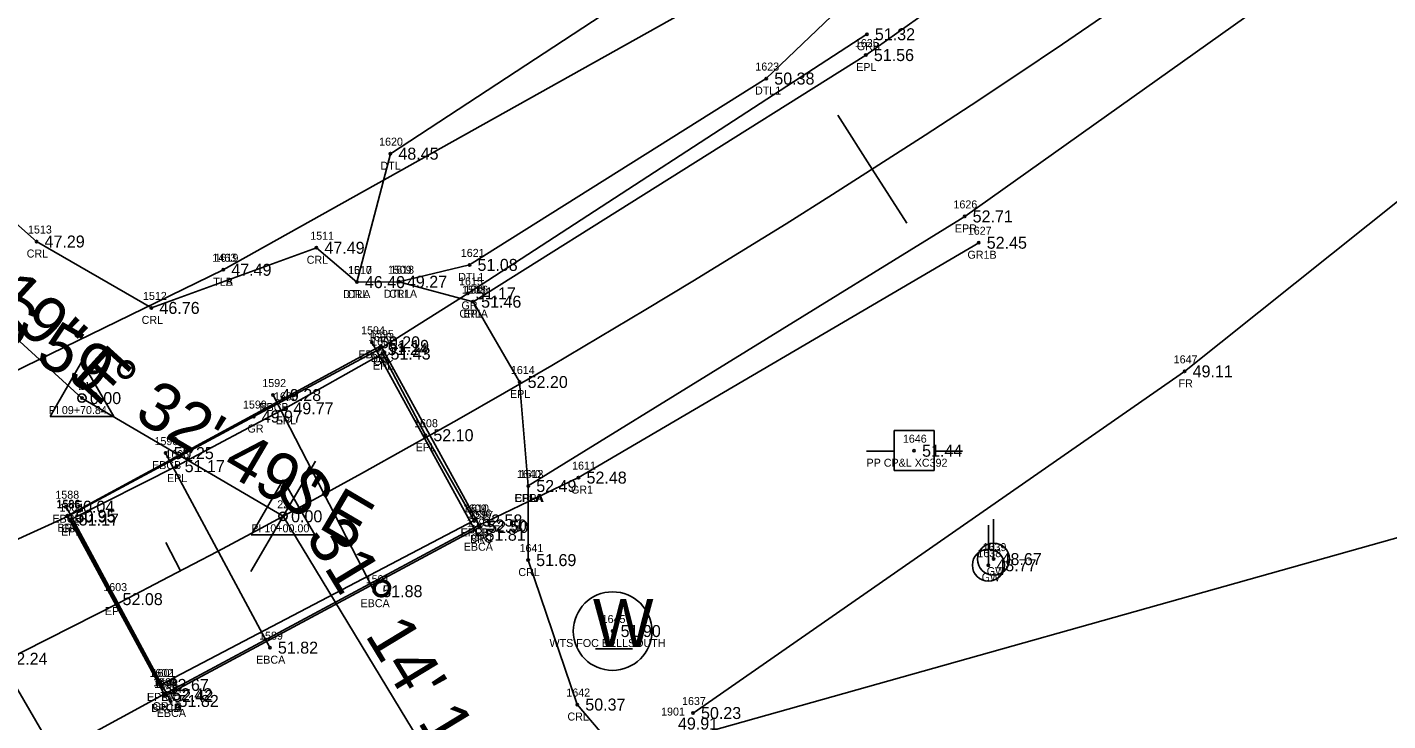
# Model space of a CAD drawing. Extents: x 2420113 to 2422887, y 845323 to 846653.
# Drawn here: x 2421748.2 to 2421918.2, y 845790.5 to 845877.2 of the extents above; entities that cross this region are included whole.
import ezdxf

# ---------------------------------------------------------------- set-up
doc = ezdxf.new("R2010")
doc.units = 0
for name, color, linetype in [('RD_EX_Bridge', 7, 'Continuous'), ('RD_EX_Bridge_txCode', 7, 'Continuous'), ('RD_EX_Fence_Other', 7, 'Continuous'), ('RD_EX_Fence_Other_txCode', 7, 'Continuous'), ('RD_EX_GuardRail', 7, 'Continuous'), ('RD_EX_GuardRail_txCode', 7, 'Continuous'), ('RD_EX_H2O', 7, 'Continuous'), ('RD_EX_H2O_txCode', 7, 'Continuous'), ('RD_EX_Road', 7, 'Continuous'), ('RD_EX_Road_txCode', 7, 'Continuous'), ('RD_EX_TX_Bridge_ELEV', 7, 'Continuous'), ('RD_EX_TX_Fence_Other_ELEV', 7, 'Continuous'), ('RD_EX_TX_GuardRail_ELEV', 7, 'Continuous'), ('RD_EX_TX_H2O_ELEV', 7, 'Continuous'), ('RD_EX_TX_Road_ELEV', 7, 'Continuous'), ('RD_EX_TX_UT_ELEV', 7, 'Continuous'), ('RD_EX_TX_VEG_ELEV', 7, 'Continuous'), ('RD_EX_UT', 7, 'Continuous'), ('RD_EX_UT_txCode', 7, 'Continuous'), ('RD_EX_VEG', 7, 'Continuous'), ('RD_EX_VEG_txCode', 7, 'Continuous'), ('RD_HC_Cl', 7, 'Continuous'), ('RD_HC_Data', 7, 'Continuous'), ('RD_HC_Data_Tic', 7, 'Continuous'), ('RD_HC_Survey_ELEV', 7, 'Continuous'), ('RD_HC_txCode', 7, 'Continuous'), ('RD_SMD_Locator', 7, 'Continuous')]:
    doc.layers.add(name, color=color, linetype=linetype)

msp = doc.modelspace()

# ---------------------------------------------------------------- linework, layer by layer
at = {"layer": 'RD_EX_Bridge'}
for p, q in [((2421804.43, 845813.73), (2421791.23, 845837.78)), ((2421791.53, 845806.67), (2421778.87, 845831.19)), ((2421778.48, 845799.61), (2421765.45, 845823.93)), ((2421766.07, 845792.95), (2421753.01, 845817.23))]:
    msp.add_line(p, q, dxfattribs=at)
msp.add_lwpolyline([(2421765.39, 845793.58), (2421753.17, 845816.1), (2421792.35, 845837.33), (2421804.76, 845814.71), (2421765.39, 845793.58)], dxfattribs=at)
at = {"layer": 'RD_EX_Fence_Other'}
msp.add_lwpolyline([(2421831.36, 845791.44), (2421892.8, 845834.15), (2422007.74, 845925.97), (2422081.95, 845988.07), (2422163.86, 846055.55), (2422242.21, 846120.9), (2422258.64, 846091.49), (2422278.16, 846056.57)], dxfattribs=at)
at = {"layer": 'RD_EX_GuardRail'}
for points in [[(2421687.56, 845786.15), (2421753.19, 845816.01), (2421776.46, 845828.5), (2421792.19, 845836.93), (2421803.2, 845843.9), (2421853.09, 845876.29)], [(2421700.48, 845761.64), (2421736.86, 845778.33), (2421765.25, 845793.79), (2421765.25, 845793.79), (2421804.57, 845814.88), (2421817.05, 845820.87), (2421867.07, 845850.23)]]:
    msp.add_lwpolyline(points, dxfattribs=at)
at = {"layer": 'RD_EX_H2O'}
for points in [[(2421803.88, 845842.86), (2421794.61, 845845.35), (2421789.35, 845845.31), (2421784.3, 845849.6), (2421763.68, 845842.08), (2421749.32, 845850.38), (2421719.73, 845876.64), (2421694.91, 845901.66), (2421677.7, 845939.02), (2421693.6, 845947.01), (2421705.85, 845990.03), (2421703.45, 845999.67)], [(2421789.35, 845845.31), (2421793.54, 845861.36), (2421830.86, 845885.86), (2421856.64, 845909.86), (2421885.29, 845955.58), (2421912.03, 845969.16), (2421958.61, 845996.32), (2421973.32, 845987.17)], [(2421794.61, 845845.35), (2421803.43, 845847.46), (2421840.52, 845870.75), (2421867.66, 845896.73), (2421896.88, 845943.67), (2421923.99, 845959.47), (2421960.72, 845976.98), (2421973.32, 845987.17)], [(2421810.77, 845819.82), (2421810.76, 845810.56), (2421816.9, 845792.5), (2421822.4, 845786.03), (2421848.72, 845738.63), (2421858.75, 845685.13), (2421860.35, 845662.88), (2421845.9, 845650.47), (2421833.11, 845629.75), (2421840.79, 845614.06), (2421848.44, 845579.41), (2421832.04, 845554.52), (2421837.19, 845498.45), (2421811.62, 845484.13), (2421811.72, 845469.11), (2421841.99, 845438.03), (2421875.97, 845424.56), (2421900.41, 845383.13), (2421915.29, 845367.51)]]:
    msp.add_lwpolyline(points, dxfattribs=at)
at = {"layer": 'RD_EX_Road'}
msp.add_line((2421764.83, 845794.95), (2421804.01, 845815.51), dxfattribs=at)
for points in [[(2421810.77, 845819.82), (2421809.69, 845832.82), (2421803.88, 845842.86), (2421852.96, 845873.69), (2421939.48, 845935.12), (2421980.78, 845967.01), (2422140.12, 846092.81), (2422210.03, 846148.43), (2422282.88, 846205.21), (2422291.79, 846212.09), (2422354.49, 846261.98), (2422400.82, 846297.88), (2422417.34, 846311.65), (2422435.4, 846324.77), (2422462.49, 846346.77), (2422472.85, 846354.85), (2422502.3, 846378.16), (2422578.05, 846437.54), (2422605.64, 846459.09), (2422626.64, 846476.17), (2422642.61, 846488.86)], [(2421810.77, 845819.82), (2421865.31, 845853.52), (2421953.26, 845916.07), (2421995.06, 845948.03), (2422068.36, 846005.98), (2422153.46, 846073.36), (2422229.55, 846134.03), (2422245.4, 846145.63), (2422297.08, 846186.88), (2422369.77, 846243.69), (2422382.04, 846253.08), (2422449.02, 846305.97), (2422517.14, 846360.1), (2422592.58, 846419.1), (2422657.51, 846470.1)], [(2421764.83, 845794.95), (2421759.07, 845805.68), (2421753.59, 845815.63), (2421766.83, 845822.3), (2421780.42, 845829.53), (2421792.55, 845836.37), (2421797.91, 845826.17), (2421804.01, 845815.51)], [(2420388.28, 845680.39), (2420441.29, 845692.04), (2420492.62, 845700.7), (2420553.92, 845707.41), (2420607.69, 845710.85), (2420682.38, 845711.26), (2420749.44, 845707.27), (2420795.12, 845703.44), (2420900.28, 845693.42), (2421017.17, 845682.19), (2421113.9, 845672.97), (2421174.87, 845668.16), (2421234.59, 845666.13), (2421293, 845667.25), (2421351.24, 845671.5), (2421419.82, 845681.17), (2421463.19, 845688.63), (2421558.82, 845713.18), (2421614.57, 845730.45), (2421670.73, 845751.42), (2421735.61, 845780.5), (2421750.75, 845787.87), (2421744.67, 845798.22), (2421739.21, 845808.11)]]:
    msp.add_lwpolyline(points, dxfattribs=at)
at = {"layer": 'RD_EX_UT'}
for p, q in [((2421861.48, 845826.74), (2421856.48, 845826.74)), ((2421856.48, 845826.74), (2421856.48, 845821.74)), ((2421861.48, 845821.74), (2421861.48, 845826.74)), ((2421853.04, 845824.18), (2421856.51, 845824.18)), ((2421861.4, 845824.18), (2421865.04, 845824.18)), ((2421856.48, 845821.74), (2421861.48, 845821.74)), ((2421868.92, 845810.68), (2421868.92, 845815.68)), ((2421868.27, 845809.92), (2421868.27, 845814.92)), ((2421819.18, 845799.48), (2421823.81, 845799.48))]:
    msp.add_line(p, q, dxfattribs=at)
for centre, radius in [((2421868.27, 845809.92), 2), ((2421868.92, 845810.68), 2), ((2421821.31, 845801.68), 4.91)]:
    msp.add_circle(centre, radius, dxfattribs=at)
at = {"layer": 'RD_EX_VEG'}
for points in [[(2420990.17, 846190.24), (2420988, 845998.32), (2421000.67, 845894.83), (2421039.72, 845794.91), (2421064.26, 845723.75), (2421180.05, 845716.6), (2421345.47, 845727.16), (2421407.77, 845719.99), (2421650.04, 845787.07), (2421772.66, 845846.85), (2421772.66, 845846.85), (2421889.56, 845912.24), (2422060.37, 846045.26), (2422197.94, 846165.23), (2422281.92, 846227.58), (2422364.58, 846286.67), (2422339.46, 846334.5)], [(2421514.28, 845601.29), (2421515.71, 845632.65), (2421540.03, 845670.81), (2421822.4, 845786.03), (2421822.4, 845786.03), (2421928.63, 845815.98), (2422026.48, 845905.33), (2422114.13, 845963.57), (2422135.16, 845938.99)]]:
    msp.add_lwpolyline(points, dxfattribs=at)
at = {"layer": 'RD_HC_Cl'}
for p, q in [((2421717.97, 845864.51), (2421754.99, 845830.81)), ((2421754.99, 845830.81), (2421780.13, 845816.03)), ((2421780.13, 845816.03), (2421802.52, 845779.12))]:
    msp.add_line(p, q, dxfattribs=at)
msp.add_arc((2421235.71, 846823.95), 1145.56, 264.46476, 308.21213, dxfattribs=at)
at = {"layer": 'RD_HC_Data'}
for p, q in [((2421751.02, 845828.52), (2421754.99, 845835.4)), ((2421754.99, 845835.4), (2421758.96, 845828.52)), ((2421751.02, 845828.52), (2421758.96, 845828.52)), ((2421776.16, 845813.73), (2421780.14, 845820.61)), ((2421780.14, 845820.61), (2421784.1, 845813.73)), ((2421776.16, 845813.73), (2421784.1, 845813.73))]:
    msp.add_line(p, q, dxfattribs=at)
for centre in [(2421754.99, 845830.81), (2421780.13, 845816.03)]:
    msp.add_circle(centre, 0.529, dxfattribs=at)
at = {"layer": 'RD_HC_Data_Tic'}
for p, q in [((2421853.77, 845859.42), (2421849.46, 845866.16)), ((2421853.77, 845859.42), (2421858.09, 845852.69)), ((2421780.13, 845816.03), (2421784.19, 845822.92)), ((2421780.13, 845816.03), (2421776.08, 845809.13)), ((2421767.33, 845809.21), (2421765.47, 845812.76))]:
    msp.add_line(p, q, dxfattribs=at)
at = {"layer": 'RD_SMD_Locator'}
for centre in [(2421853.09, 845876.29), (2421852.96, 845873.69), (2421840.52, 845870.75), (2421793.54, 845861.36), (2421865.31, 845853.52), (2421749.32, 845850.38), (2421784.3, 845849.6), (2421867.07, 845850.23), (2421803.43, 845847.46), (2421772.66, 845846.85), (2421772.66, 845846.85), (2421789.35, 845845.31), (2421789.35, 845845.31), (2421794.61, 845845.35), (2421794.61, 845845.35), (2421803.2, 845843.9), (2421803.88, 845842.86), (2421803.88, 845842.86), (2421763.68, 845842.08), (2421791.23, 845837.78), (2421792.35, 845837.33), (2421792.19, 845836.93), (2421792.55, 845836.37), (2421892.8, 845834.15), (2421809.69, 845832.82), (2421754.99, 845830.81), (2421778.87, 845831.19), (2421780.42, 845829.53), (2421776.46, 845828.5), (2421797.91, 845826.17), (2421765.45, 845823.93), (2421858.99, 845824.23), (2421766.83, 845822.3), (2421817.05, 845820.87), (2421810.77, 845819.82), (2421810.77, 845819.82), (2421810.77, 845819.82), (2421753.01, 845817.23), (2421753.17, 845816.1), (2421753.19, 845816.01), (2421753.59, 845815.63), (2421780.13, 845816.03), (2421804.01, 845815.51), (2421804.01, 845815.51), (2421804.43, 845813.73), (2421804.57, 845814.88), (2421804.76, 845814.71), (2421810.76, 845810.56), (2421868.27, 845809.92), (2421868.92, 845810.68), (2421791.53, 845806.67), (2421759.07, 845805.68), (2421821.31, 845801.68), (2421778.48, 845799.61), (2421764.83, 845794.95), (2421764.83, 845794.95), (2421765.25, 845793.79), (2421765.25, 845793.79), (2421765.39, 845793.58), (2421765.39, 845793.58), (2421766.07, 845792.95), (2421816.9, 845792.5), (2421831.36, 845791.44)]:
    msp.add_circle(centre, 0.15, dxfattribs=at)

# ---------------------------------------------------------------- texts
at = {"layer": 'RD_EX_Bridge_txCode'}
for s, p in [('1594', (2421789.88, 845838.78)), ('1595', (2421791, 845838.33)), ('EBCB', (2421789.53, 845835.78)), ('BRC', (2421791.1, 845835.33)), ('1592', (2421777.53, 845832.19)), ('EBCB', (2421777.17, 845829.19)), ('1590', (2421764.06, 845824.93)), ('EBCB', (2421763.75, 845821.93)), ('1588', (2421751.67, 845818.23)), ('1586', (2421751.8, 845817.1)), ('EBCB', (2421751.31, 845815.23)), ('1593', (2421803.08, 845814.73)), ('1597', (2421803.41, 845815.71)), ('BRC', (2421751.92, 845814.1)), ('BRC', (2421803.5, 845812.71)), ('EBCA', (2421802.71, 845811.73)), ('1591', (2421790.46, 845807.67)), ('EBCA', (2421789.81, 845804.67)), ('1589', (2421777.13, 845800.61)), ('EBCA', (2421776.76, 845797.61)), ('1582', (2421764.04, 845794.58)), ('1598', (2421764.04, 845794.58)), ('1587', (2421764.72, 845793.95)), ('BRCA', (2421763.65, 845791.58)), ('BRCB', (2421763.66, 845791.58)), ('EBCA', (2421764.35, 845790.95))]:
    msp.add_text(s, height=1, dxfattribs=at).set_placement(p)
at = {"layer": 'RD_EX_Fence_Other_txCode'}
for s, p in [('1647', (2421891.43, 845835.15)), ('FR', (2421892.04, 845832.15)), ('1637', (2421829.99, 845792.44)), ('1901', (2421827.37, 845791.12))]:
    msp.add_text(s, height=1, dxfattribs=at).set_placement(p)
at = {"layer": 'RD_EX_GuardRail_txCode'}
for s, p in [('GRB', (2421851.83, 845874.29)), ('1627', (2421865.7, 845851.23)), ('GR1B', (2421865.66, 845848.23)), ('1615', (2421802.12, 845844.9)), ('GR', (2421802.42, 845841.9)), ('1600', (2421790.75, 845837.93)), ('GR', (2421791.41, 845834.93)), ('1599', (2421775.12, 845829.5)), ('GR', (2421775.68, 845826.5)), ('1611', (2421816.25, 845821.87)), ('GR1', (2421816.11, 845818.87)), ('1585', (2421751.85, 845817.01)), ('1596', (2421803.2, 845815.88)), ('GR', (2421752.41, 845814.01)), ('GR1', (2421803.63, 845812.88)), ('1469', (2421763.88, 845794.79)), ('1583', (2421763.9, 845794.79)), ('GR1A', (2421763.81, 845791.79)), ('GR1B', (2421763.83, 845791.79))]:
    msp.add_text(s, height=1, dxfattribs=at).set_placement(p)
at = {"layer": 'RD_EX_H2O_txCode'}
for s, p in [('1623', (2421839.15, 845871.75)), ('DTL1', (2421839.11, 845868.75)), ('1620', (2421792.13, 845862.36)), ('DTL', (2421792.29, 845859.36)), ('1513', (2421748.25, 845851.38)), ('1511', (2421783.52, 845850.6)), ('CRL', (2421748.09, 845848.38)), ('1621', (2421802.34, 845848.46)), ('CRL', (2421783.08, 845847.6)), ('1510', (2421788.25, 845846.31)), ('1617', (2421788.27, 845846.31)), ('1509', (2421793.22, 845846.35)), ('1618', (2421793.52, 845846.35)), ('DTL1', (2421802.02, 845845.46)), ('1512', (2421762.62, 845843.08)), ('DTLA', (2421787.62, 845843.31)), ('CRL', (2421788.13, 845843.31)), ('DTL1A', (2421792.71, 845843.35)), ('CRL', (2421793.38, 845843.35)), ('1508', (2421802.49, 845843.86)), ('CRL', (2421762.45, 845840.08)), ('CRLA', (2421802.16, 845840.86)), ('1640', (2421809.36, 845820.82)), ('CRLA', (2421809.06, 845817.82)), ('1641', (2421809.68, 845811.56)), ('CRL', (2421809.53, 845808.56)), ('1642', (2421815.53, 845793.5)), ('CRL', (2421815.67, 845790.5))]:
    msp.add_text(s, height=1, dxfattribs=at).set_placement(p)
at = {"layer": 'RD_EX_Road_txCode'}
for s, p in [('1625', (2421851.59, 845874.69)), ('EPL', (2421851.75, 845871.69)), ('1626', (2421863.91, 845854.52)), ('EPR', (2421864.08, 845851.52)), ('1616', (2421802.77, 845843.86)), ('EPL', (2421802.67, 845840.86)), ('1607', (2421791.14, 845837.37)), ('EPL', (2421791.35, 845834.37)), ('1614', (2421808.6, 845833.82)), ('1606', (2421778.99, 845830.53)), ('EPL', (2421808.49, 845830.82)), ('EPL', (2421779.22, 845827.53)), ('1608', (2421796.5, 845827.17)), ('1605', (2421765.42, 845823.3)), ('EPL', (2421796.71, 845824.17)), ('EPL', (2421765.62, 845820.3)), ('1612', (2421809.69, 845820.82)), ('1613', (2421809.69, 845820.82)), ('EPRA', (2421809.06, 845817.82)), ('EPLA', (2421809.08, 845817.82)), ('1604', (2421752.18, 845816.63)), ('1609', (2421802.6, 845816.51)), ('1610', (2421802.88, 845816.51)), ('EPL', (2421752.38, 845813.63)), ('EPRB', (2421802.31, 845813.51)), ('EPLB', (2421802.33, 845813.51)), ('1603', (2421757.66, 845806.68)), ('EPL', (2421757.86, 845803.68)), ('1602', (2421763.42, 845795.95)), ('1601', (2421763.7, 845795.95)), ('EPRA', (2421763.11, 845792.95)), ('EPLA', (2421763.13, 845792.95))]:
    msp.add_text(s, height=1, dxfattribs=at).set_placement(p)
at = {"layer": 'RD_EX_TX_Bridge_ELEV'}
for s, p in [('50.20', (2421792.23, 845837.03)), ('51.19', (2421793.35, 845836.58)), ('49.28', (2421779.87, 845830.44)), ('50.25', (2421766.45, 845823.18)), ('50.04', (2421754.01, 845816.48)), ('50.95', (2421754.17, 845815.35)), ('52.50', (2421805.76, 845813.96)), ('51.81', (2421805.43, 845812.98)), ('51.88', (2421792.53, 845805.92)), ('51.82', (2421779.48, 845798.86)), ('52.42', (2421766.39, 845792.83)), ('52.42', (2421766.39, 845792.83)), ('51.82', (2421767.07, 845792.2))]:
    msp.add_text(s, height=1.5, dxfattribs=at).set_placement(p)
at = {"layer": 'RD_EX_TX_Fence_Other_ELEV'}
for s, p in [('49.11', (2421893.8, 845833.4)), ('50.23', (2421832.36, 845790.69)), ('49.91', (2421829.48, 845789.37))]:
    msp.add_text(s, height=1.5, dxfattribs=at).set_placement(p)
at = {"layer": 'RD_EX_TX_GuardRail_ELEV'}
for s, p in [('51.32', (2421854.09, 845875.54)), ('52.45', (2421868.07, 845849.48)), ('51.17', (2421804.2, 845843.15)), ('51.24', (2421793.19, 845836.18)), ('49.97', (2421777.46, 845827.75)), ('52.48', (2421818.05, 845820.12)), ('50.95', (2421754.19, 845815.26)), ('52.50', (2421805.57, 845814.13)), ('52.42', (2421766.25, 845793.04)), ('52.42', (2421766.25, 845793.04))]:
    msp.add_text(s, height=1.5, dxfattribs=at).set_placement(p)
at = {"layer": 'RD_EX_TX_H2O_ELEV'}
for s, p in [('50.38', (2421841.52, 845870)), ('48.45', (2421794.54, 845860.61)), ('47.29', (2421750.32, 845849.63)), ('47.49', (2421785.3, 845848.85)), ('51.08', (2421804.43, 845846.71)), ('46.40', (2421790.35, 845844.56)), ('46.40', (2421790.35, 845844.56)), ('49.27', (2421795.61, 845844.6)), ('49.27', (2421795.61, 845844.6)), ('46.76', (2421764.68, 845841.33)), ('51.46', (2421804.88, 845842.11)), ('52.49', (2421811.77, 845819.07)), ('51.69', (2421811.76, 845809.81)), ('50.37', (2421817.9, 845791.75))]:
    msp.add_text(s, height=1.5, dxfattribs=at).set_placement(p)
at = {"layer": 'RD_EX_TX_Road_ELEV'}
for s, p in [('51.56', (2421853.96, 845872.94)), ('52.71', (2421866.31, 845852.77)), ('51.46', (2421804.88, 845842.11)), ('51.43', (2421793.55, 845835.62)), ('52.20', (2421810.69, 845832.07)), ('49.77', (2421781.42, 845828.78)), ('52.10', (2421798.91, 845825.42)), ('51.17', (2421767.83, 845821.55)), ('52.49', (2421811.77, 845819.07)), ('52.49', (2421811.77, 845819.07)), ('51.17', (2421754.59, 845814.88)), ('52.58', (2421805.01, 845814.76)), ('52.58', (2421805.01, 845814.76)), ('52.08', (2421760.07, 845804.93)), ('52.24', (2421745.67, 845797.47)), ('52.67', (2421765.83, 845794.2)), ('52.67', (2421765.83, 845794.2))]:
    msp.add_text(s, height=1.5, dxfattribs=at).set_placement(p)
at = {"layer": 'RD_EX_TX_UT_ELEV'}
for s, p in [('48.77', (2421869.27, 845809.17)), ('48.67', (2421869.92, 845809.93)), ('51.90', (2421822.31, 845800.94))]:
    msp.add_text(s, height=1.5, dxfattribs=at).set_placement(p)
at = {"layer": 'RD_EX_TX_VEG_ELEV'}
msp.add_text('47.49', height=1.5, dxfattribs=at).set_placement((2421773.66, 845846.1))
msp.add_text('47.49', height=1.5, dxfattribs=at).set_placement((2421773.66, 845846.1))
at = {"layer": 'RD_EX_UT'}
msp.add_text('W', height=6, dxfattribs=at).set_placement((2421818.85, 845799.68))
at = {"layer": 'RD_EX_UT_txCode'}
for s, p in [('1646', (2421857.59, 845825.23)), ('PP CP&L XC392', (2421853.05, 845822.23)), ('1638', (2421866.9, 845810.92)), ('1639', (2421867.55, 845811.68)), ('GW', (2421867.43, 845807.92)), ('GW', (2421868.07, 845808.68)), ('1645', (2421819.94, 845802.69)), ('WTS FOC BELLSOUTH', (2421813.43, 845799.69))]:
    msp.add_text(s, height=1, dxfattribs=at).set_placement(p)
at = {"layer": 'RD_EX_VEG_txCode'}
for s, p in [('1463', (2421771.29, 845847.85)), ('1619', (2421771.57, 845847.85)), ('TLA', (2421771.4, 845844.85)), ('TLB', (2421771.41, 845844.85))]:
    msp.add_text(s, height=1, dxfattribs=at).set_placement(p)
at = {"layer": 'RD_HC_Data'}
for s, rotation, p in [('S 47%%d 41\' 19" E', 317.6887, (2421717.68, 845866.13)), ('S 59%%d 32\' 49" E', 329.5471, (2421742.43, 845839.35)), ('S 31%%d 14\' 19" E', 301.2387, (2421778.91, 845819.97))]:
    msp.add_text(s, height=6, rotation=rotation, dxfattribs=at).set_placement(p)
at = {"layer": 'RD_HC_Survey_ELEV'}
for s, p in [('0.00', (2421755.99, 845830.06)), ('51.44', (2421859.99, 845823.48)), ('0.00', (2421781.13, 845815.28))]:
    msp.add_text(s, height=1.5, dxfattribs=at).set_placement(p)
at = {"layer": 'RD_HC_txCode'}
for s, p in [('21', (2421754.54, 845831.81)), ('PI 09+70.84', (2421750.85, 845828.81)), ('22', (2421779.4, 845817.03)), ('PI 10+00.00', (2421776.16, 845814.03))]:
    msp.add_text(s, height=1, dxfattribs=at).set_placement(p)

doc.saveas('drawing.dxf')
